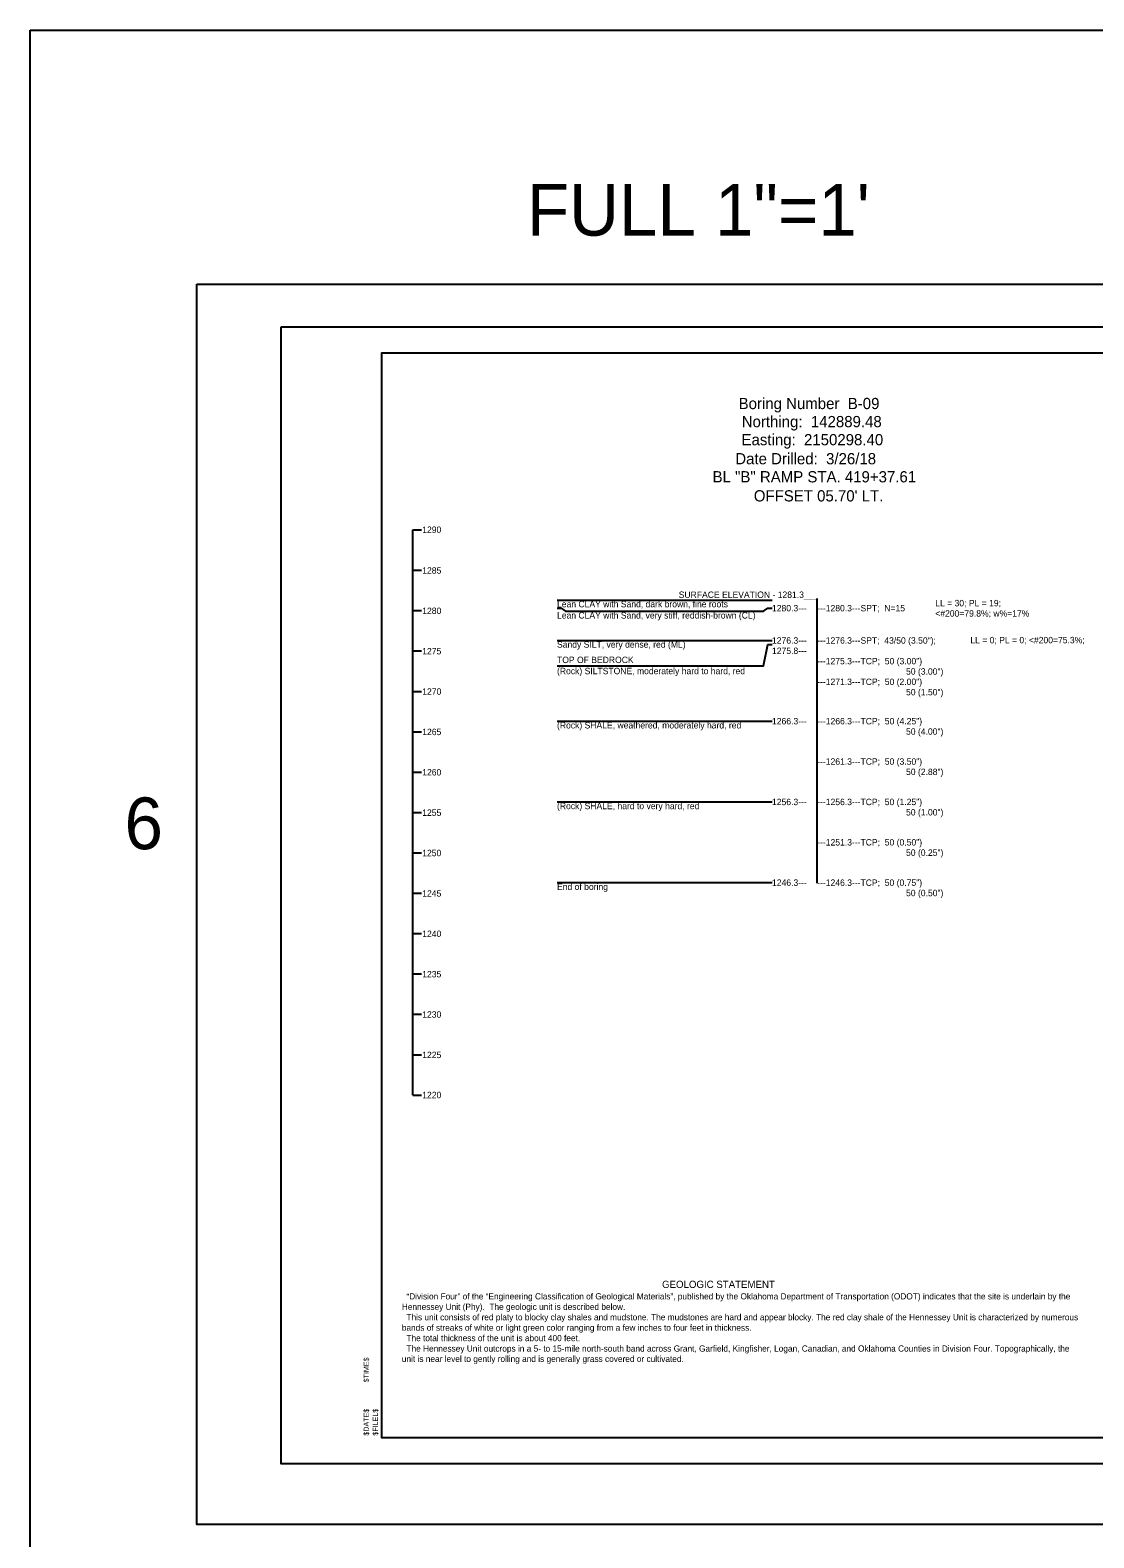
# Model space of a CAD drawing. Extents: x 2150162 to 2150245, y 143729 to 143865.
# Drawn here: x 2150203.4 to 2150224, y 143835.89 to 143865.06 of the extents above; entities that cross this region are included whole.
import ezdxf

# ---------------------------------------------------------------- set-up
doc = ezdxf.new("R2010")
doc.units = 0
for name, color, linetype in [('Default', 7, 'Continuous'), ('S', 7, 'Continuous'), ('SHT_Plot_Shape_Full', 7, 'Continuous'), ('SHT_Plot_Shape_Half', 7, 'Continuous'), ('SHT_Plot_Stamp', 7, 'Continuous'), ('SHT_Sheet_Border', 7, 'Continuous'), ('Text', 7, 'Continuous')]:
    doc.layers.add(name, color=color, linetype=linetype)

# ---------------------------------------------------------------- blocks, each defined once
blk = doc.blocks.new('Stamp_Plot_Stamp')
at = {"layer": 'SHT_Plot_Stamp'}
for s, p in [('$TIME$', (1.695, 1.572)), ('$DATE$', (1.695, 0.542)), ('$FILEL$', (1.873, 0.542))]:
    blk.add_text(s, height=0.1, rotation=90, dxfattribs=at).set_placement(p)

msp = doc.modelspace()

# ---------------------------------------------------------------- linework, layer by layer
at = {"layer": 'Default'}
msp.add_line((2150210.813, 143844.453), (2150210.813, 143855.391), dxfattribs=at)
for points in [[(2150210.813, 143855.391), (2150210.979, 143855.391)], [(2150210.813, 143854.61), (2150210.979, 143854.61)], [(2150213.604, 143854.033), (2150217.771, 143854.033)], [(2150213.604, 143853.876), (2150213.687, 143853.876), (2150213.771, 143853.816), (2150217.604, 143853.816), (2150217.687, 143853.876), (2150217.771, 143853.876)], [(2150218.631, 143854.06), (2150218.631, 143848.557)], [(2150210.813, 143853.828), (2150210.979, 143853.828)], [(2150210.813, 143853.047), (2150210.979, 143853.047)], [(2150210.813, 143853.047), (2150210.979, 143853.047)], [(2150213.604, 143853.251), (2150217.771, 143853.251)], [(2150213.604, 143852.759), (2150217.604, 143852.759), (2150217.687, 143853.173), (2150217.771, 143853.173)], [(2150210.813, 143852.266), (2150210.979, 143852.266)], [(2150213.604, 143851.689), (2150217.771, 143851.689)], [(2150210.813, 143851.485), (2150210.979, 143851.485)], [(2150210.813, 143850.703), (2150210.979, 143850.703)], [(2150213.604, 143850.126), (2150217.771, 143850.126)], [(2150210.813, 143849.922), (2150210.979, 143849.922)], [(2150210.813, 143849.141), (2150210.979, 143849.141)], [(2150210.813, 143848.36), (2150210.979, 143848.36)], [(2150213.604, 143848.564), (2150217.771, 143848.564)], [(2150210.813, 143847.578), (2150210.979, 143847.578)], [(2150210.813, 143846.797), (2150210.979, 143846.797)], [(2150210.813, 143846.016), (2150210.979, 143846.016)], [(2150210.813, 143845.235), (2150210.979, 143845.235)], [(2150210.813, 143844.453), (2150210.979, 143844.453)]]:
    msp.add_lwpolyline(points, dxfattribs=at)
at = {"layer": 'S'}
msp.add_lwpolyline([(2150203.404, 143865.061), (2150245.24, 143865.061), (2150245.24, 143729.315), (2150203.404, 143729.315)], close=True, dxfattribs=at)
at = {"layer": 'SHT_Plot_Shape_Full'}
msp.add_lwpolyline([(2150206.628, 143860.145), (2150242.628, 143860.145), (2150242.628, 143836.145), (2150206.628, 143836.145)], close=True, dxfattribs=at)
at = {"layer": 'SHT_Plot_Shape_Half'}
msp.add_lwpolyline([(2150208.265, 143859.32), (2150242.265, 143859.32), (2150242.265, 143837.32), (2150208.265, 143837.32)], close=True, dxfattribs=at)
at = {"layer": 'SHT_Sheet_Border'}
msp.add_lwpolyline([(2150241.715, 143837.82), (2150210.215, 143837.82), (2150210.215, 143858.82), (2150241.715, 143858.82)], close=True, dxfattribs=at)

# ---------------------------------------------------------------- block references
at = {"layer": 'SHT_Plot_Stamp'}
msp.add_blockref('Stamp_Plot_Stamp', (2150208.265, 143837.32), dxfattribs=at)

# ---------------------------------------------------------------- texts
at = {"layer": 'Default'}
for s, height, p in [('Boring Number  B-09', 0.217, (2150217.12, 143857.728)), ('Northing:  142889.48', 0.217, (2150217.18, 143857.378)), ('Easting:  2150298.40', 0.217, (2150217.176, 143857.028)), ('Date Drilled:  3/26/18', 0.217, (2150217.055, 143856.66)), ('BL "B" RAMP STA. 419+37.61', 0.217, (2150216.616, 143856.31)), ("OFFSET 05.70' LT.", 0.217, (2150217.414, 143855.941)), ('1290', 0.124, (2150210.995, 143855.332)), ('1285', 0.124, (2150210.995, 143854.544)), ('SURFACE ELEVATION - 1281.3___', 0.124, (2150215.96, 143854.074)), ('1280', 0.124, (2150210.995, 143853.763)), ('Lean CLAY with Sand, dark brown, fine roots', 0.124, (2150213.604, 143853.892)), ('1280.3---', 0.124, (2150217.766, 143853.814)), ('---1280.3---SPT;  N=15', 0.124, (2150218.641, 143853.814)), ('LL = 30; PL = 19;', 0.124, (2150220.927, 143853.912)), ('Lean CLAY with Sand, very stiff, reddish-brown (CL)', 0.124, (2150213.604, 143853.675)), ('<#200=79.8%; w%=17%', 0.124, (2150220.927, 143853.712)), ('1276.3---', 0.124, (2150217.766, 143853.189)), ('---1276.3---SPT;  43/50 (3.50");', 0.124, (2150218.641, 143853.189)), ('LL = 0; PL = 0; <#200=75.3%%%;', 0.124, (2150221.606, 143853.196)), ('1275', 0.124, (2150210.995, 143852.982)), ('Sandy SILT, very dense, red (ML)', 0.124, (2150213.604, 143853.111)), ('1275.8---', 0.124, (2150217.766, 143852.989)), ('TOP OF BEDROCK', 0.124, (2150213.604, 143852.813)), ('(Rock) SILTSTONE, moderately hard to hard, red', 0.124, (2150213.604, 143852.598)), ('---1275.3---TCP;  50 (3.00")', 0.124, (2150218.641, 143852.789)), ('50 (3.00")', 0.124, (2150220.361, 143852.589)), ('---1271.3---TCP;  50 (2.00")', 0.124, (2150218.641, 143852.389)), ('1270', 0.124, (2150210.995, 143852.201)), ('50 (1.50")', 0.124, (2150220.361, 143852.189)), ('1265', 0.124, (2150210.995, 143851.419)), ('(Rock) SHALE, weathered, moderately hard, red', 0.124, (2150213.604, 143851.548)), ('1266.3---', 0.124, (2150217.766, 143851.627)), ('---1266.3---TCP;  50 (4.25")', 0.124, (2150218.641, 143851.627)), ('50 (4.00")', 0.124, (2150220.361, 143851.427)), ('---1261.3---TCP;  50 (3.50")', 0.124, (2150218.641, 143850.846)), ('1260', 0.124, (2150210.995, 143850.638)), ('50 (2.88")', 0.124, (2150220.361, 143850.646)), ('(Rock) SHALE, hard to very hard, red', 0.124, (2150213.604, 143849.986)), ('1256.3---', 0.124, (2150217.766, 143850.064)), ('---1256.3---TCP;  50 (1.25")', 0.124, (2150218.641, 143850.064)), ('1255', 0.124, (2150210.995, 143849.857)), ('50 (1.00")', 0.124, (2150220.361, 143849.864)), ('1250', 0.124, (2150210.995, 143849.076)), ('---1251.3---TCP;  50 (0.50")', 0.124, (2150218.641, 143849.283)), ('50 (0.25")', 0.124, (2150220.361, 143849.083)), ('1246.3---', 0.124, (2150217.766, 143848.502)), ('---1246.3---TCP;  50 (0.75")', 0.124, (2150218.641, 143848.502)), ('1245', 0.124, (2150210.995, 143848.294)), ('End of boring', 0.124, (2150213.604, 143848.423)), ('50 (0.50")', 0.124, (2150220.361, 143848.302)), ('1240', 0.124, (2150210.995, 143847.513)), ('1235', 0.124, (2150210.995, 143846.732)), ('1230', 0.124, (2150210.995, 143845.951)), ('1225', 0.124, (2150210.995, 143845.169)), ('1220', 0.124, (2150210.995, 143844.393))]:
    msp.add_text(s, height=height, dxfattribs=at).set_placement(p)
at = {"layer": 'S'}
for s, p in [('FULL 1"=1\'', (2150213.021, 143861.084)), ('6', (2150205.231, 143849.212))]:
    msp.add_text(s, height=1, dxfattribs=at).set_placement(p)
at = {"layer": 'Text'}
for s, height, p in [('GEOLOGIC STATEMENT', 0.14, (2150215.637, 143840.721)), ('Hennessey Unit (Phy).  The geologic unit is described below. ', 0.12, (2150210.6, 143840.297)), ('  “Division Four” of the “Engineering Classification of Geological Materials”, published by the Oklahoma Department of Transportation (ODOT) indicates that the site is underlain by the ', 0.12, (2150210.6, 143840.499)), ('  This unit consists of red platy to blocky clay shales and mudstone. The mudstones are hard and appear blocky. The red clay shale of the Hennessey Unit is characterized by numerous ', 0.12, (2150210.6, 143840.095)), ('bands of streaks of white or light green color ranging from a few inches to four feet in thickness. ', 0.12, (2150210.6, 143839.893)), ('  The total thickness of the unit is about 400 feet.', 0.12, (2150210.6, 143839.691)), ('  The Hennessey Unit outcrops in a 5- to 15-mile north-south band across Grant, Garfield, Kingfisher, Logan, Canadian, and Oklahoma Counties in Division Four. Topographically, the ', 0.12, (2150210.6, 143839.489)), ('unit is near level to gently rolling and is generally grass covered or cultivated.', 0.12, (2150210.6, 143839.289))]:
    msp.add_text(s, height=height, dxfattribs=at).set_placement(p)

doc.saveas('drawing.dxf')
